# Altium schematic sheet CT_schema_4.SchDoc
size 287 x 169 mm
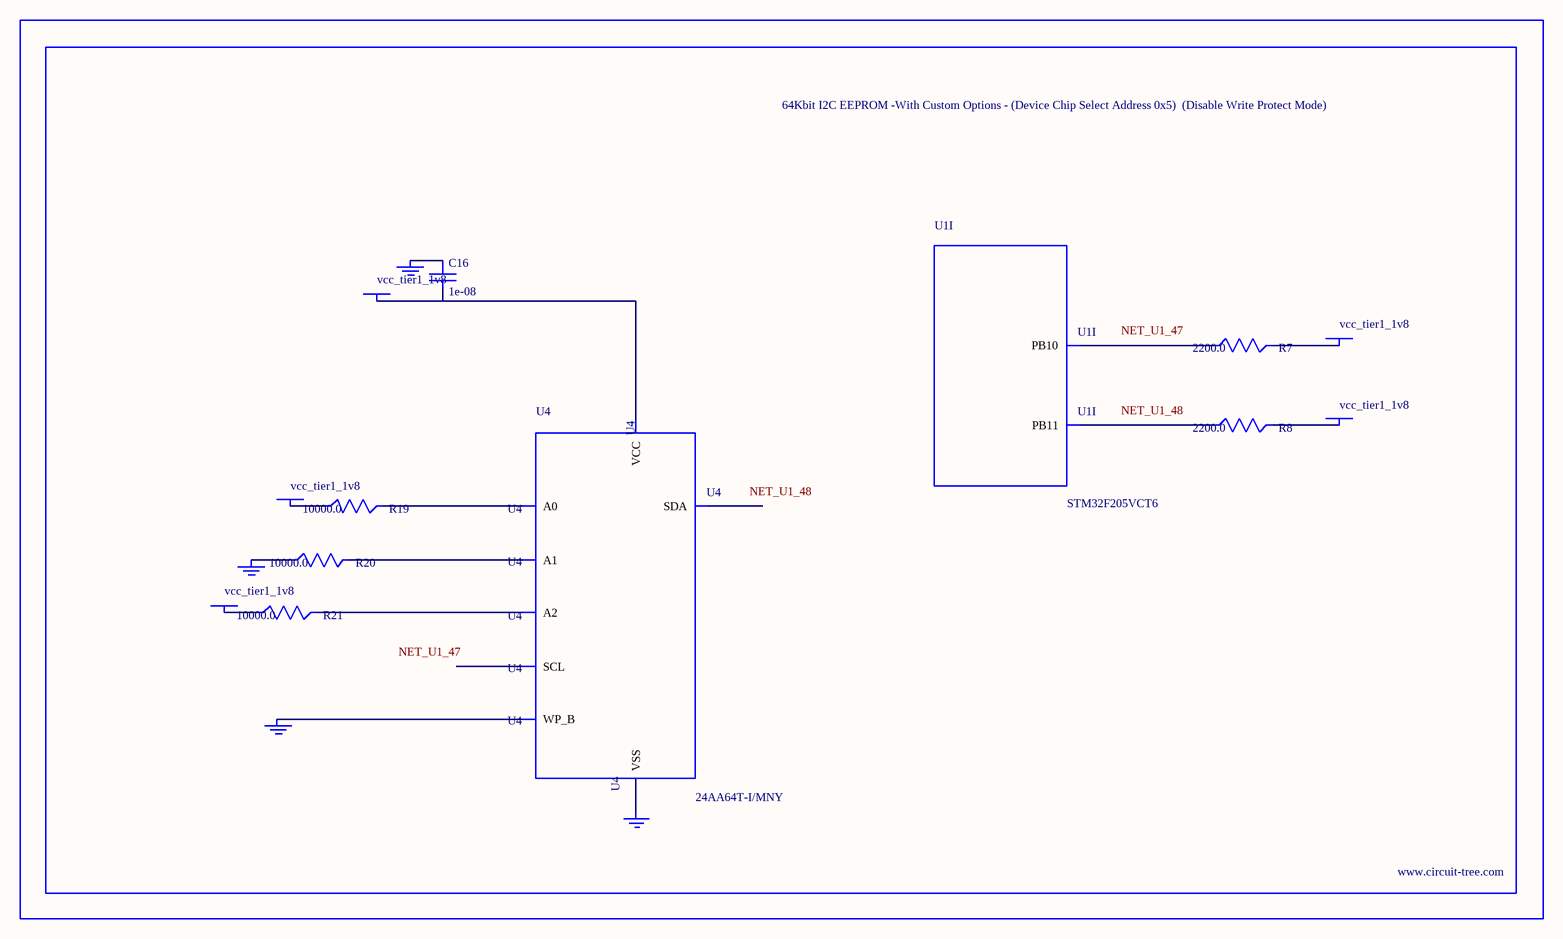
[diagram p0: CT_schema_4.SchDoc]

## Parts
BORDER3  (no value)
C16  1e-08  [C0402]
GND_INSTANCE_3_0  (no value)
GND_INSTANCE_3_1  (no value)
GND_INSTANCE_3_2  (no value)
GND_INSTANCE_3_3  (no value)
POWER_INSTANCE_3_0  vcc_tier1_1v8
POWER_INSTANCE_3_1  vcc_tier1_1v8
POWER_INSTANCE_3_2  vcc_tier1_1v8
POWER_INSTANCE_3_3  vcc_tier1_1v8
POWER_INSTANCE_3_4  vcc_tier1_1v8
R7  2200.0  [R0603]
R8  2200.0  [R0603]
R19  10000.0  [R0603]
R20  10000.0  [R0603]
R21  10000.0  [R0603]
U1  STM32F205VCT6  [LQFP100]  (part I of 10)
U4  24AA64T-I/MNY  [TDFN-8/6MM]

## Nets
NetC16_1: C16.1 GND_INSTANCE_3_2.0(GND)
NetC16_2: C16.2 POWER_INSTANCE_3_2.0(PWR) U4.8(VCC)
NetGND_INSTANCE_3_0_0: GND_INSTANCE_3_0.0(GND) R20.1
NetGND_INSTANCE_3_1_0: GND_INSTANCE_3_1.0(GND) U4.7(WP_B)
NetGND_INSTANCE_3_3_0: GND_INSTANCE_3_3.0(GND) U4.4(VSS)
NetPOWER_INSTANCE_3_0_0: POWER_INSTANCE_3_0.0(PWR) R19.1
NetPOWER_INSTANCE_3_1_0: POWER_INSTANCE_3_1.0(PWR) R21.1
NetPOWER_INSTANCE_3_3_0: POWER_INSTANCE_3_3.0(PWR) R7.2
NetPOWER_INSTANCE_3_4_0: POWER_INSTANCE_3_4.0(PWR) R8.2
NetR7_1: R7.1 U1.47(PB10)
NetR8_1: R8.1 U1.48(PB11)
NetR19_2: R19.2 U4.1(A0)
NetR20_2: R20.2 U4.2(A1)
NetR21_2: R21.2 U4.3(A2)

Not connected (* = marked no-connect by the designer): U4 5(SDA) 6(SCL)

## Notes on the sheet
- Labels drawn without touching a wire or pin: NET_U1_47, NET_U1_48

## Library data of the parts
BORDER3 = BORDER_PAGE3
C16 = C0402C103K3RAC
GND_INSTANCE_3_0-GND_INSTANCE_3_3 = GND
POWER_INSTANCE_3_0-POWER_INSTANCE_3_4 = PWR
R7 R8 = RC0603JR-072K2L
R19-R21 = RC0603JR-0710KL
